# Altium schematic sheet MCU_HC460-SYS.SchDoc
size A4; CompanyName: 广州立功科技股份有限公司; DocumentNumber: 5; SheetNumber: 5; SheetTotal: 15; PageSetup: Record=PageOptions|CenterHorizontal=True|CenterVertical=True|PrintScale=1.00|XCorrection=1.00|YCorrection=1.00|PrintKind=0|BorderSize=5000000|LeftOffset=0|BottomOffset=0|Orientation=2|PaperLength=1000|PaperWidth=1000|Scale=100|PaperSource=7|PrintQuality=600|MediaType=1|DitherType=10|PaperKind=A4|PrintScaleMode=1; DesignDate: 2021.1; SheetName: MCU_HC460_SYS; SheetVersion: Rev.A; SheetDescription: 单片机最小系统
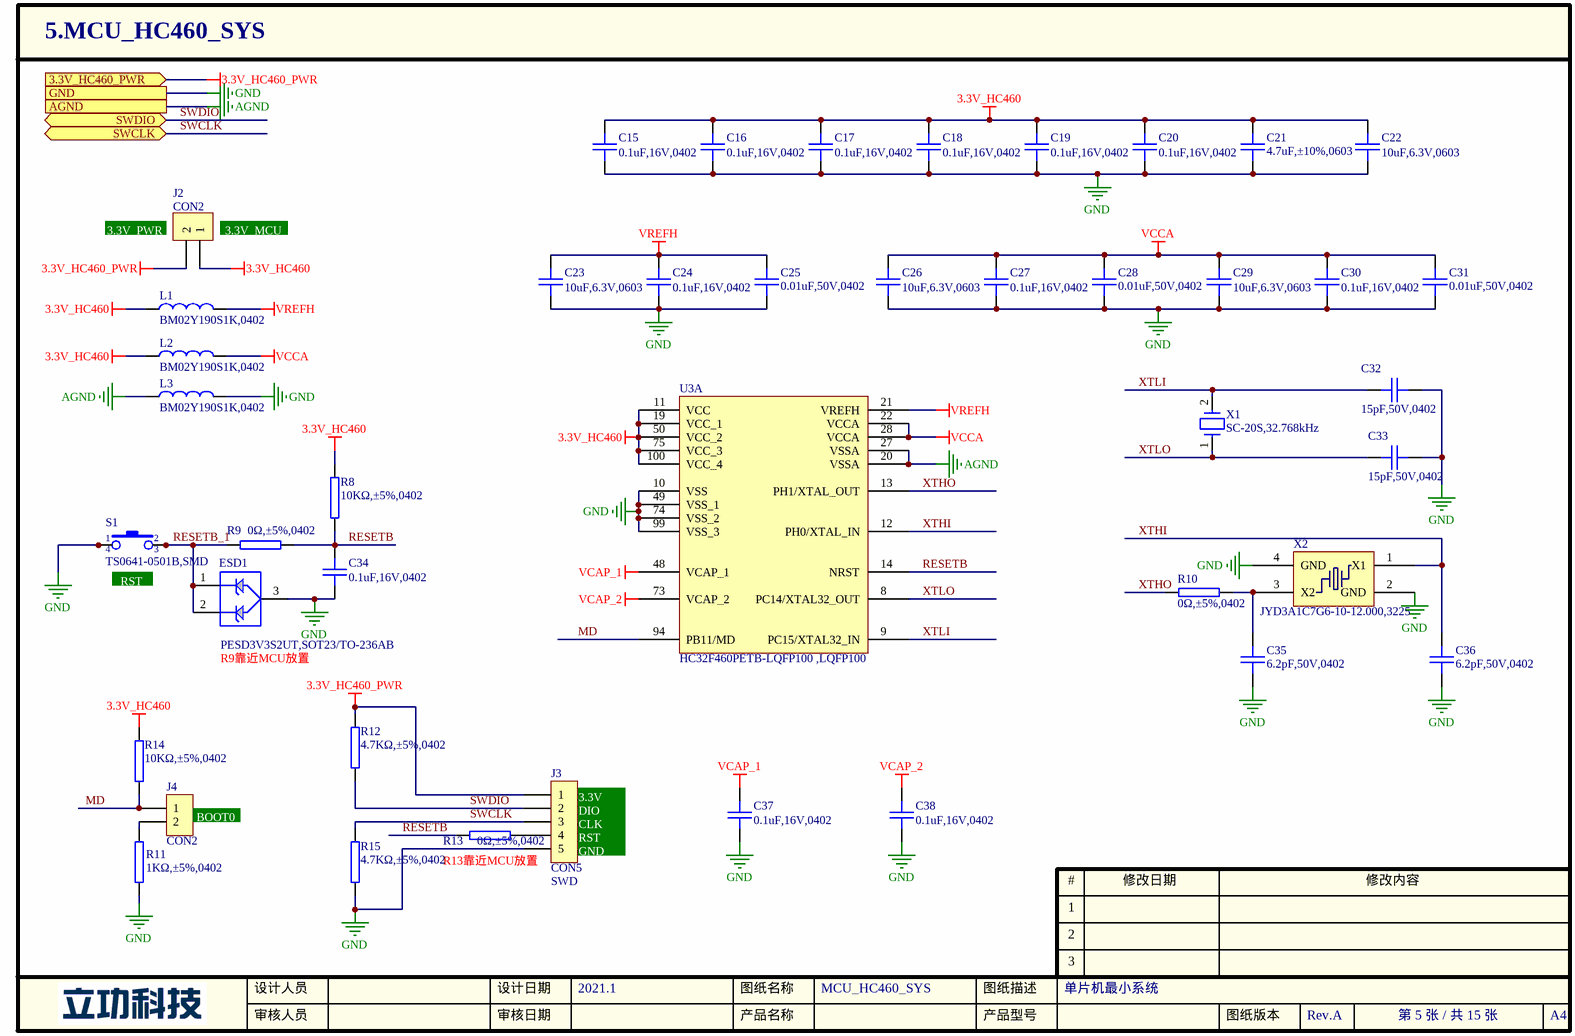
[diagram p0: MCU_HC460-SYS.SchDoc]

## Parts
C15  0.1uF,16V,0402  [0402C]
C16  0.1uF,16V,0402  [0402C]
C17  0.1uF,16V,0402  [0402C]
C18  0.1uF,16V,0402  [0402C]
C19  0.1uF,16V,0402  [0402C]
C20  0.1uF,16V,0402  [0402C]
C21  4.7uF,±10%,0603  [0603C]
C22  10uF,6.3V,0603  [0603C]
C23  10uF,6.3V,0603  [0603C]
C24  0.1uF,16V,0402  [0402C]
C25  0.01uF,50V,0402  [0402C]
C26  10uF,6.3V,0603  [0603C]
C27  0.1uF,16V,0402  [0402C]
C28  0.01uF,50V,0402  [0402C]
C29  10uF,6.3V,0603  [0603C]
C30  0.1uF,16V,0402  [0402C]
C31  0.01uF,50V,0402  [0402C]
C32  15pF,50V,0402  [0402C]
C33  15pF,50V,0402  [0402C]
C34  0.1uF,16V,0402  [0402C]
C35  6.2pF,50V,0402  [0402C]
C36  6.2pF,50V,0402  [0402C]
C37  0.1uF,16V,0402  [0402C]
C38  0.1uF,16V,0402  [0402C]
ESD1  PESD3V3S2UT,SOT23/TO-236AB  [SOT-23]
J2  CON2  [SIP-2-2.54]
J3  CON5  [SIP-5-2.54]
J4  CON2  [SIP-2-2.54]
L1  BM02Y190S1K,0402  [0402L]
L2  BM02Y190S1K,0402  [0402L]
L3  BM02Y190S1K,0402  [0402L]
R8  10KΩ,±5%,0402  [0402R]
R9  0Ω,±5%,0402  [0402R]
R10  0Ω,±5%,0402  [0402R]
R11  1KΩ,±5%,0402  [0402R]
R12  4.7KΩ,±5%,0402  [0402R]
R13  0Ω,±5%,0402  [0402R]
R14  10KΩ,±5%,0402  [0402R]
R15  4.7KΩ,±5%,0402  [0402R]
S1  TS0641-0501B,SMD  [KEY-6S]
U3  HC32F460PETB-LQFP100 / ,LQFP100  [QFP50P1600X1600X160-100N]  (part A of 2)
X1  SC-20S,32.768kHz  [XTAL205X120X60-2N]
X2  JYD3A1C7G6-10-12.000,3225  [OSCCC250X320X80-4N]

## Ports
3.3V_HC460_PWR (in), AGND, GND, SWCLK, SWDIO

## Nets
3.3V_HC460: C15.1 C16.1 C17.1 C18.1 C19.1 C20.1 C21.1 C22.1 J2.1 L1.1 L2.1 R8.2 R14.2 U3.11(VCC) U3.19(VCC_1) U3.50(VCC_2) U3.75(VCC_3) U3.100(VCC_4)
3.3V_HC460_PWR: J2.2 J3.1 R12.2 ; port 3.3V_HC460_PWR
AGND: L3.1 U3.20(VSSA) U3.27(VSSA) ; port AGND
GND: C15.2 C16.2 C17.2 C18.2 C19.2 C20.2 C21.2 C22.2 C23.2 C24.2 C25.2 C26.2 C27.2 C28.2 C29.2 C30.2 C31.2 C32.2 C33.2 C34.2 C35.2 C36.2 C37.2 C38.2 ESD1.3 J3.5 L3.2 R11.1 R15.1 S1.1 S1.4 U3.10(VSS) U3.49(VSS_1) U3.74(VSS_2) U3.99(VSS_3) X2.2(GND) X2.4(GND) ; port GND
VCAP_1: C37.1 U3.48(VCAP_1)
VCAP_2: C38.1 U3.73(VCAP_2)
VCCA: C26.1 C27.1 C28.1 C29.1 C30.1 C31.1 L2.2 U3.22(VCCA) U3.28(VCCA)
VREFH: C23.1 C24.1 C25.1 L1.2 U3.21(VREFH)
MD: J4.1 R14.1 U3.94(PB11/MD)
RESETB: C34.1 R8.1 R9.1 R13.2 U3.14(NRST)
RESETB_1: ESD1.1 ESD1.2 R9.2 S1.2 S1.3
SWCLK: J3.3 R15.2 ; port SWCLK
SWDIO: J3.2 R12.1 ; port SWDIO
XTHI: C36.1 U3.12(PH0/XTAL_IN) X2.1(X1)
XTHO: R10.1 U3.13(PH1/XTAL_OUT)
XTLI: C32.1 U3.9(PC15/XTAL32_IN) X1.2
XTLO: C33.1 U3.8(PC14/XTAL32_OUT) X1.1
NetC35_1: C35.1 R10.2 X2.3(X2)
NetJ3_4: J3.4 R13.1
NetJ4_2: J4.2 R11.2

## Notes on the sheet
- (near J2) 3.3V_PWR
- (near J2) 3.3V_MCU
- (near S1) RST
- (near ESD1) R9靠近MCU放置
- (near J4) BOOT0
- (near J3) 3.3V
- (near J3) DIO
- (near J3) CLK
- (near J3) RST
- (near J3) GND
- (near R13) R13靠近MCU放置
- (near J3) SWD

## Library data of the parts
C15-C20 C24 C27 C30 C34 C37 C38 = 02.01.00263: GRM155R71C104KA88D,0402,MURATA,0.1uF,X7R,±10%,16V,; 旧物料代码: 1.02.17.0006; 名称: 电容; 封装: 0402; 贴片和直插: SMT; 器件优选方案: 通用物料
C21 = 02.01.00521: GRM188C71C475KE21D,0603,MURATA,4.7uF,X7S,16V,±10%,MURATA; 名称: 电容; 封装: 0603; 贴片和直插: SMT; PCB备注: 200714CZY; 器件优选方案: 通用物料
C22 C23 C26 C29 = 02.01.00155: GRM188R60J106M****,0603,MURATA,10uF,X5R,±20%,6.3V,; 旧物料代码: 1.02.01.0065; 名称: 电容; 封装: 0603; 贴片和直插: SMT; 器件优选方案: 不推荐使用
C25 C28 C31 = 02.01.00275: GRM155R71H103KA88D,0402,MURATA,0.01uF,X7R,±10%,50V,; 旧物料代码: 1.02.17.0019; 名称: 电容; 封装: 0402; 贴片和直插: SMT; 器件优选方案: 通用物料
C32 C33 = 02.01.00262: GRM1555C1H150JA01D,0402,MURATA,15pF,C0G,±5%,50V,; 旧物料代码: 1.02.17.0005; 名称: 电容; 封装: 0402; 贴片和直插: SMT; 器件优选方案: 通用物料
C35 C36 = 02.01.00335: GRM1555C1H6R2CA01D,0402,MURATA,6.2pF,C0G,±0.25pF,50V,; 旧物料代码: 1.02.17.0094; 名称: 电容; 封装: 0402; 贴片和直插: SMT; PCB备注: 无数据手册，依据采购部提供的信息添加的封装。; 器件优选方案: 通用物料
ESD1 = 09.04.00156: PESD3V3S2UT,SOT23/TO-236AB,NEXPERIA,; 旧物料代码: 1.05.10.0361; 名称: 二极管; 贴片和直插: SMT; 器件优选方案: 通用物料
J2 J4 = CON2: Connector; 物料代码: 18.01.00032
J3 = CON5: Connector; 物料代码: 18.01.00032
L1-L3 = 03.03.00030: BM02Y190S1K,0402,GAUSSTEK,1KΩ,300mA,DCR1.2Ω; 旧物料代码: 1.03.03.0033; 名称: 磁珠; 封装: 0402; 贴片和直插: SMT; PCB备注: 180226ZW; 器件优选方案: 通用物料
R8 R14 = 01.01.00001: RTT02103JTH,0402,RALEC,10KΩ,±5%,1/16W; 旧物料代码: 1.01.17.0006; 名称: 电阻; 封装: 0402; 贴片和直插: SMT; 器件优选方案: 通用物料
R9 R10 R13 = 01.01.00004: RTT02000JTH,0402,RALEC,0Ω,±5%,1/16W,; 旧物料代码: 1.01.17.0004; 名称: 电阻; 封装: 0402; 贴片和直插: SMT; 器件优选方案: 通用物料
R11 = 01.01.00007: RTT02102JTH,0402,RALEC,1KΩ,±5%,1/16W,; 旧物料代码: 1.01.17.0022; 名称: 电阻; 封装: 0402; 贴片和直插: SMT; 器件优选方案: 通用物料
R12 R15 = 01.01.00003: RTT02472JTH,0402,RALEC,4.7KΩ,±5%,1/16W,; 旧物料代码: 1.01.17.0019; 名称: 电阻; 封装: 0402; 贴片和直插: SMT; 环保状态: RoHS2.0+REACH; 器件优选方案: 通用物料; 生产单位: PCS
S1 = 17.01.00005: TS0641-0501B,SMD,DAILYLON,黑色,卷带装,6*6*5.0mm,; 名称: 轻触开关; 贴片和直插: SMT; 器件优选方案: 通用物料; 旧物料代码: 1.09.01.0003
U3 = 08.20.00166: HC32F460PETB-LQFP100 / ,LQFP100,华大HDSC; 名称: 集成电路; 封装: LQFP-100; 厂商: HDSC; 贴片和直插: SMT; PCB备注: 210219ZW; 器件优选方案: 待导入物料
X1 = 12.02.00196: SC-20S,32.768kHz,12.5pF,±20ppm,SMD2012,SII; 旧物料代码: 1.07.01.0071; 名称: 晶体; 封装: SMT; PCB备注: 180227ZW; 器件优选方案: 不推荐使用
X2 = 12.02.00162: JYD3A1C7G6-10-12.000,3225,JYEG,12MHz,±10ppm,10pF,-40~85℃,; 旧物料代码: 1.07.01.0032; 名称: 晶体; 封装: SMT; PCB备注: 151229lmd171128ZW; 器件优选方案: 通用物料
